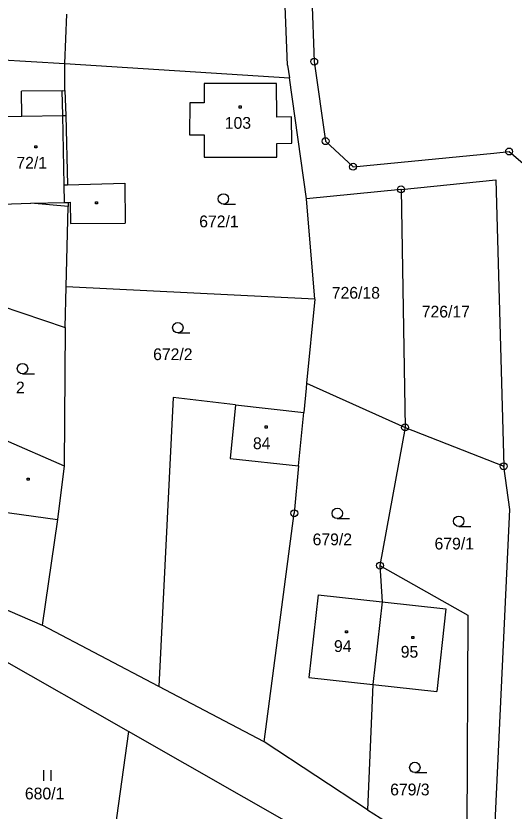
# Model space of a CAD drawing. Extents: x -794142 to -791199, y -1109267 to -1105626.
# Drawn here: x -793326.7 to -793254.8, y -1108046.6 to -1107931.8 of the extents above; entities that cross this region are included whole.
import ezdxf

# ---------------------------------------------------------------- set-up
doc = ezdxf.new("R2010")
doc.units = 0
for name, color, linetype in [('Vrstva 1', 7, 'Continuous'), ('Vrstva 14', 7, 'Continuous'), ('Vrstva 15', 7, 'Continuous'), ('Vrstva 2', 7, 'Continuous'), ('Vrstva 23', 7, 'Continuous'), ('Vrstva 25', 7, 'Continuous'), ('Vrstva 28', 7, 'Continuous')]:
    doc.layers.add(name, color=color, linetype=linetype)

msp = doc.modelspace()

# ---------------------------------------------------------------- linework, layer by layer
at = {"layer": 'Vrstva 1'}
for p, q in [((-793287.48, -1107938.89), (-793288.69, -1107909.44)), ((-793284.15, -1107925.1), (-793283.64, -1107938.37)), ((-793319.65, -1107938.63), (-793319.35, -1107931.52)), ((-793340.09, -1107937.44), (-793319.65, -1107938.63)), ((-793283.64, -1107938.37), (-793282, -1107949.87)), ((-793319.67, -1107942.57), (-793319.65, -1107938.63)), ((-793319.65, -1107938.63), (-793287.22, -1107940.72)), ((-793287.48, -1107938.89), (-793287.22, -1107940.72)), ((-793289.09, -1107941.55), (-793299.53, -1107941.53)), ((-793299.53, -1107941.53), (-793299.53, -1107944.33)), ((-793289.03, -1107946.38), (-793289.09, -1107941.55)), ((-793284.77, -1107958.2), (-793287.22, -1107940.72)), ((-793320.03, -1107942.58), (-793325.92, -1107942.66)), ((-793325.86, -1107946.24), (-793325.92, -1107942.66)), ((-793320.03, -1107942.58), (-793319.67, -1107942.57)), ((-793319.67, -1107942.57), (-793319.5, -1107946.15)), ((-793301.62, -1107944.33), (-793301.63, -1107948.94)), ((-793299.53, -1107944.33), (-793301.62, -1107944.33)), ((-793329.08, -1107946.32), (-793325.86, -1107946.24)), ((-793319.5, -1107946.15), (-793319.24, -1107956.16)), ((-793286.91, -1107946.37), (-793289.03, -1107946.38)), ((-793286.85, -1107950.18), (-793286.91, -1107946.37)), ((-793301.63, -1107948.94), (-793299.53, -1107948.94)), ((-793299.53, -1107948.94), (-793299.53, -1107952.2)), ((-793282, -1107949.87), (-793278.03, -1107953.57)), ((-793289.04, -1107950.19), (-793286.85, -1107950.18)), ((-793289.03, -1107952.16), (-793289.04, -1107950.19)), ((-793299.53, -1107952.2), (-793289.03, -1107952.16)), ((-793278.03, -1107953.57), (-793257.69, -1107951.58)), ((-793257.69, -1107951.58), (-793255.49, -1107951.36)), ((-793255.49, -1107951.36), (-793253.53, -1107953.07)), ((-793271.1, -1107956.83), (-793257.42, -1107955.46)), ((-793257.42, -1107955.46), (-793256.28, -1107996.83)), ((-793319.24, -1107956.16), (-793311, -1107955.92)), ((-793311, -1107955.92), (-793310.94, -1107961.72)), ((-793271.1, -1107956.83), (-793284.77, -1107958.2)), ((-793271.1, -1107956.83), (-793270.51, -1107991.22)), ((-793328.76, -1107958.95), (-793324.56, -1107958.84)), ((-793319.17, -1107959.31), (-793324.56, -1107958.84)), ((-793319.18, -1107958.71), (-793318.88, -1107958.7)), ((-793319.18, -1107958.71), (-793319.17, -1107959.31)), ((-793318.88, -1107958.7), (-793318.81, -1107961.75)), ((-793283.53, -1107972.68), (-793284.77, -1107958.2)), ((-793319.45, -1107970.92), (-793319.17, -1107959.31)), ((-793318.81, -1107961.75), (-793310.94, -1107961.72)), ((-793319.59, -1107976.8), (-793319.45, -1107970.92)), ((-793283.53, -1107972.68), (-793319.45, -1107970.92)), ((-793283.53, -1107972.68), (-793284.75, -1107984.84)), ((-793329, -1107973.61), (-793319.59, -1107976.8)), ((-793319.59, -1107976.8), (-793319.74, -1107996.75)), ((-793284.75, -1107984.84), (-793284.8, -1107985.54)), ((-793284.75, -1107984.84), (-793270.51, -1107991.22)), ((-793284.8, -1107985.54), (-793285.14, -1107989.06)), ((-793304.02, -1107986.91), (-793306.05, -1108028.64)), ((-793294.98, -1107987.94), (-793304.02, -1107986.91)), ((-793294.98, -1107987.94), (-793285.14, -1107989.06)), ((-793285.89, -1107996.76), (-793285.14, -1107989.06)), ((-793270.51, -1107991.22), (-793274.15, -1108011.17)), ((-793270.51, -1107991.22), (-793256.28, -1107996.83)), ((-793328.57, -1107992.9), (-793319.74, -1107996.75)), ((-793319.74, -1107996.75), (-793320.7, -1108004.53)), ((-793285.89, -1107996.76), (-793286.51, -1108003.61)), ((-793255.37, -1108003.06), (-793256.28, -1107996.83)), ((-793329.63, -1108003.28), (-793320.7, -1108004.53)), ((-793290.84, -1108036.62), (-793286.51, -1108003.61)), ((-793257.94, -1108057.03), (-793255.37, -1108003.06)), ((-793320.7, -1108004.53), (-793322.91, -1108019.8)), ((-793274.15, -1108011.17), (-793273.84, -1108016.4)), ((-793274.15, -1108011.17), (-793261.46, -1108018.35)), ((-793340.28, -1108012.21), (-793322.91, -1108019.8)), ((-793310.44, -1108035.15), (-793347.39, -1108014.1)), ((-793283.05, -1108015.39), (-793284.39, -1108027.33)), ((-793283.05, -1108015.39), (-793273.84, -1108016.4)), ((-793273.84, -1108016.4), (-793275.15, -1108028.35)), ((-793273.84, -1108016.4), (-793264.62, -1108017.41)), ((-793264.62, -1108017.41), (-793265.91, -1108029.37)), ((-793261.46, -1108018.35), (-793261.6, -1108053.2)), ((-793306.05, -1108028.64), (-793322.91, -1108019.8)), ((-793284.39, -1108027.33), (-793275.15, -1108028.35)), ((-793290.84, -1108036.62), (-793306.05, -1108028.64)), ((-793275.15, -1108028.35), (-793275.93, -1108046.46)), ((-793275.15, -1108028.35), (-793265.91, -1108029.37)), ((-793310.44, -1108035.15), (-793314.07, -1108060.76)), ((-793282.44, -1108051.11), (-793310.44, -1108035.15)), ((-793275.93, -1108046.46), (-793290.84, -1108036.62)), ((-793275.93, -1108046.46), (-793269.7, -1108050.39))]:
    msp.add_line(p, q, dxfattribs=at)
at = {"layer": 'Vrstva 2'}
for p, q in [((-793319.95, -1107946.16), (-793320.03, -1107942.58)), ((-793325.86, -1107946.24), (-793319.95, -1107946.16)), ((-793319.95, -1107946.16), (-793319.5, -1107946.15)), ((-793319.74, -1107956.17), (-793319.95, -1107946.16)), ((-793319.74, -1107956.17), (-793319.24, -1107956.16)), ((-793319.68, -1107958.72), (-793319.74, -1107956.17)), ((-793324.56, -1107958.84), (-793319.68, -1107958.72)), ((-793319.68, -1107958.72), (-793319.18, -1107958.71)), ((-793294.98, -1107987.94), (-793295.77, -1107995.71)), ((-793295.77, -1107995.71), (-793285.89, -1107996.76))]:
    msp.add_line(p, q, dxfattribs=at)
at = {"layer": 'Vrstva 23'}
for p, q in [((-793296.75, -1107958.97), (-793295, -1107958.97)), ((-793303.33, -1107977.56), (-793301.58, -1107977.56)), ((-793325.76, -1107983.48), (-793324.01, -1107983.48)), ((-793280.3, -1108004.38), (-793278.55, -1108004.38)), ((-793262.77, -1108005.52), (-793261.02, -1108005.52)), ((-793322.66, -1108042.25), (-793322.66, -1108040.75)), ((-793321.66, -1108040.75), (-793321.66, -1108042.25)), ((-793269.11, -1108041.08), (-793267.36, -1108041.08))]:
    msp.add_line(p, q, dxfattribs=at)
for centre in [(-793296.75, -1107958.22), (-793303.33, -1107976.81), (-793325.76, -1107982.73), (-793280.3, -1108003.63), (-793262.77, -1108004.77), (-793269.11, -1108040.33)]:
    msp.add_circle(centre, 0.75, dxfattribs=at)
at = {"layer": 'Vrstva 25'}
for p, q in [((-793294.47, -1107944.78), (-793294.17, -1107944.78)), ((-793294.47, -1107945.08), (-793294.47, -1107944.78)), ((-793294.17, -1107945.08), (-793294.47, -1107945.08)), ((-793294.17, -1107944.78), (-793294.17, -1107945.08)), ((-793324, -1107950.52), (-793323.7, -1107950.52)), ((-793324, -1107950.82), (-793324, -1107950.52)), ((-793323.7, -1107950.82), (-793324, -1107950.82)), ((-793323.7, -1107950.52), (-793323.7, -1107950.82)), ((-793315.22, -1107958.62), (-793314.92, -1107958.62)), ((-793315.22, -1107958.92), (-793315.22, -1107958.62)), ((-793314.92, -1107958.92), (-793315.22, -1107958.92)), ((-793314.92, -1107958.62), (-793314.92, -1107958.92)), ((-793290.74, -1107991.01), (-793290.44, -1107991.01)), ((-793290.74, -1107991.31), (-793290.74, -1107991.01)), ((-793290.44, -1107991.01), (-793290.44, -1107991.31)), ((-793290.44, -1107991.31), (-793290.74, -1107991.31)), ((-793325.1, -1107998.56), (-793324.8, -1107998.56)), ((-793325.1, -1107998.86), (-793325.1, -1107998.56)), ((-793324.8, -1107998.86), (-793325.1, -1107998.86)), ((-793324.8, -1107998.56), (-793324.8, -1107998.86)), ((-793279.12, -1108020.58), (-793278.82, -1108020.58)), ((-793279.12, -1108020.88), (-793279.12, -1108020.58)), ((-793278.82, -1108020.88), (-793279.12, -1108020.88)), ((-793278.82, -1108020.58), (-793278.82, -1108020.88)), ((-793269.55, -1108021.4), (-793269.25, -1108021.4)), ((-793269.55, -1108021.7), (-793269.55, -1108021.4)), ((-793269.25, -1108021.7), (-793269.55, -1108021.7)), ((-793269.25, -1108021.4), (-793269.25, -1108021.7))]:
    msp.add_line(p, q, dxfattribs=at)
at = {"layer": 'Vrstva 28'}
for centre, radius in [((-793283.64, -1107938.37), 0.5), ((-793283.64, -1107938.37), 0.01), ((-793282, -1107949.87), 0.5), ((-793282, -1107949.87), 0.01), ((-793255.49, -1107951.36), 0.5), ((-793255.49, -1107951.36), 0.01), ((-793278.03, -1107953.57), 0.5), ((-793278.03, -1107953.57), 0.01), ((-793271.1, -1107956.83), 0.5), ((-793271.1, -1107956.83), 0.01), ((-793270.51, -1107991.22), 0.5), ((-793270.51, -1107991.22), 0.01), ((-793256.28, -1107996.83), 0.5), ((-793256.28, -1107996.83), 0.01), ((-793286.51, -1108003.61), 0.5), ((-793286.51, -1108003.61), 0.01), ((-793274.15, -1108011.17), 0.5), ((-793274.15, -1108011.17), 0.01)]:
    msp.add_circle(centre, radius, dxfattribs=at)

# ---------------------------------------------------------------- texts
at = {"layer": 'Vrstva 14'}
for s, p in [('672/1', (-793300.24, -1107962.31)), ('726/18', (-793281.099, -1107972.62)), ('726/17', (-793268.106, -1107975.34)), ('672/2', (-793306.896, -1107981.5)), ('2', (-793326.707, -1107986.31)), ('679/2', (-793283.866, -1108008.24)), ('679/1', (-793266.26, -1108008.85)), ('679/3', (-793272.667, -1108044.37)), ('680/1', (-793325.412, -1108044.95))]:
    msp.add_text(s, height=1.7, dxfattribs=at).set_placement(p)
at = {"layer": 'Vrstva 15'}
for s, p in [('103', (-793296.549, -1107948.08)), ('72/1', (-793326.64, -1107953.84)), ('84', (-793292.482, -1107994.36)), ('94', (-793280.783, -1108023.66)), ('95', (-793271.143, -1108024.48))]:
    msp.add_text(s, height=1.7, dxfattribs=at).set_placement(p)

doc.saveas('drawing.dxf')
